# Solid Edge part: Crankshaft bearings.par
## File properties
Author: KULL
Template: Iso Metric Part.par
Last saved by: KULL
Revision: 9
Application: Solid Edge
Accuracy: 0,990
Face Style: Model Default
Fill Style: Normal
Coef. of Thermal Exp: 0.0
Thermal Conductivity: 0.0
Specific Heat: 0.0
Modulus of Elasticity: 0.0
Poisson's Ratio: 0.0
Yield Stress: 0.0
Ultimate Stress: 0.0
Elongation: 0.0
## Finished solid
Body 1: sheet body, 4 faces, 40 edges, 40 vertices.
  Faces by surface: plane 4
  Edges by curve: circle 20, line 20
Body 2: solid body, 20 faces, 20 edges, 0 vertices, 2 separate solids.
  Faces by surface: torus 10, cylinder 6, plane 4
  Edges by curve: circle 20
Bounding box of the edges (mm; curved faces can reach further): 3.800 x 16.000 x 16.000, from (-53.3, -8, 30.6638) to (-49.5, 8, 46.6638).
Cylindrical faces by radius (mm): R3 x1, R4.8 x2, R6.7 x2, R8 x1
Toroidal faces (ring radius, tube radius in mm): R3.2 r0.2 x2, R4.6 r0.2 x2, R5.7049 r1.5 x2, R6.9 r0.2 x2, R7.8 r0.2 x2
Planar faces by outward normal: +x 2, -x 2
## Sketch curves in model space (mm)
line (-49.7659, 0, 38.6638) -> (-59.0976, 0, 38.6638)
line (-51.4, 0, 44.3688) -> (-55.1535, 0, 44.3688)
circle centre (-49.4, 0, 38.6638) radius 5
circle centre (-49.4, 0, 38.6638) radius 3
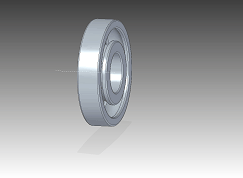
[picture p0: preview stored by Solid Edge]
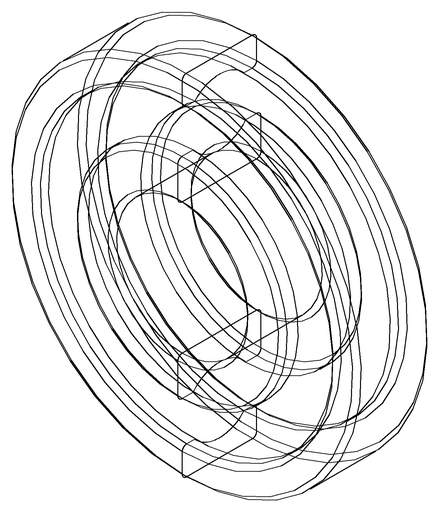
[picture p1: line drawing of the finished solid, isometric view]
